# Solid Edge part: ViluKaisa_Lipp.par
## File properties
Author: kaisa
Template: Iso Metric Part.par
Last saved by: kaisa
Revision: 4
Application: Solid Edge
Accuracy: 0.990
Username: kaisa
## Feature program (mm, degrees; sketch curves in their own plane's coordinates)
thicken "Thicken_1"  Distance1 = 0.1 mm
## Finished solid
Body 1: solid body, 6 faces, 12 edges, 8 vertices.
  Faces by surface: spline 5, offset 1
  Edges by curve: curve on surface 8, spline 4
Body 2: sheet body, 1 face, 4 edges, 4 vertices.
  Faces by surface: spline 1
  Edges by curve: spline 4
Bounding box of the edges (mm; curved faces can reach further): 88.011 x 23.755 x 5.694, from (-0.058, -13.2367, -0.0563) to (87.9534, 10.5179, 5.6375).
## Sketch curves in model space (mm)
spline (0, 10.3136, 0) -> (44.378, 5.0276, 0) -> (86.8655, 4.8496, 0)
spline (0, -7.2535, 0) -> (43.2284, -12.948, 0) -> (86.1017, -4.3746, 0)
spline (0, 0, 0) -> (47.6691, 0, 4.4533) -> (87.8974, 0, 5.5088)
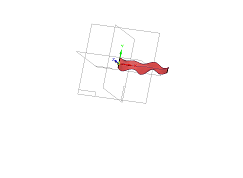
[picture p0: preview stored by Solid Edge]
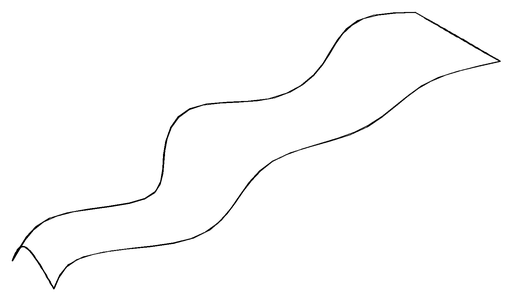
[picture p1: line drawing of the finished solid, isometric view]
